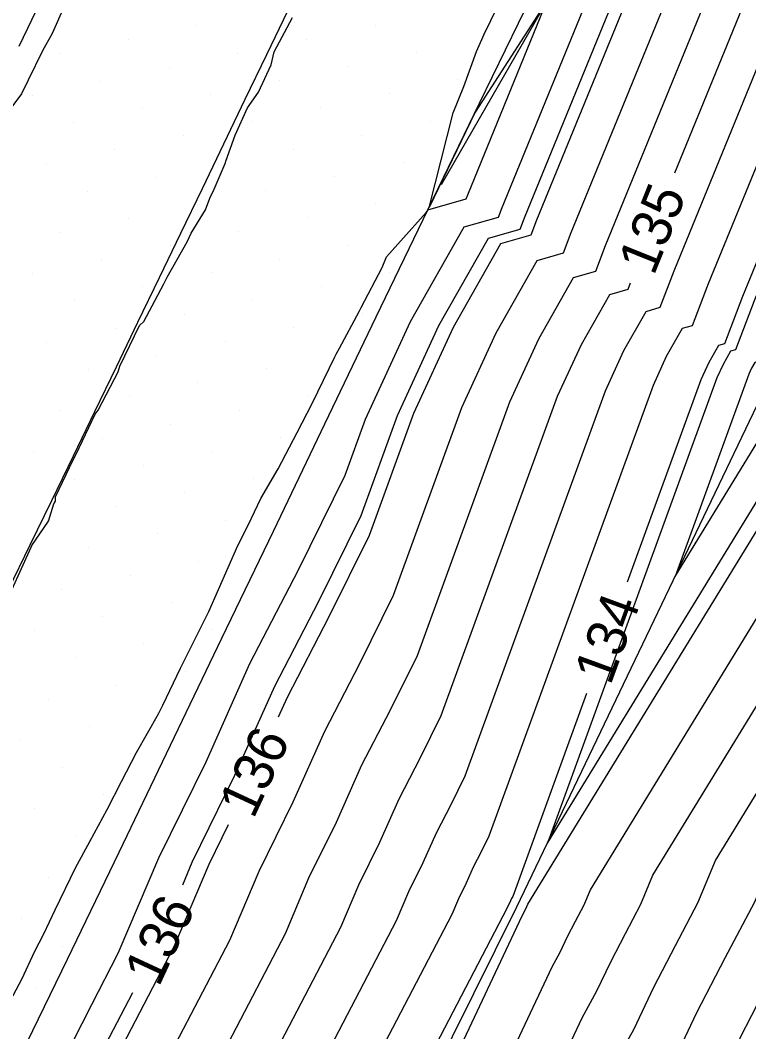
# Model space of a CAD drawing. Extents: x 2354170 to 2357230, y 866100 to 868290.
# Drawn here: x 2355241.8 to 2355278.6, y 866227 to 866278.1 of the extents above; entities that cross this region are included whole.
import ezdxf

# ---------------------------------------------------------------- set-up
doc = ezdxf.new("R2010")
doc.units = 0
for name, color, linetype in [('Default', 7, 'Continuous'), ('DTM Contours Major', 7, 'Continuous'), ('DTM Contours Major Text', 7, 'Continuous'), ('DTM Contours Minor', 7, 'Continuous'), ('DTM Contours Minor Text', 7, 'Continuous'), ('Exist DTM Breakline', 7, 'Continuous'), ('Exist DTM Scan Elevation Point', 7, 'Continuous'), ('Exist Roads EOP', 7, 'Continuous'), ('PH Exist DTM Breakline', 7, 'Continuous')]:
    doc.layers.add(name, color=color, linetype=linetype)

msp = doc.modelspace()

# ---------------------------------------------------------------- linework, layer by layer
at = {"layer": 'Default'}
for points in [[(2355317.189, 866360.801), (2355314.828, 866356.466), (2355312.404, 866351.964), (2355306.176, 866339.18), (2355300.829, 866329.165), (2355292.501, 866312.087), (2355288.744, 866303.483), (2355283.253, 866292.207), (2355282.594, 866289.072), (2355278.504, 866279.405), (2355274.815, 866270.385)], [(2355312.705, 866340.884), (2355312.471, 866340.403), (2355302.62, 866321.951), (2355298.281, 866313.055), (2355291.505, 866297.534), (2355288.645, 866291.66), (2355287.471, 866286.079), (2355280.19, 866268.873), (2355278.258, 866264.148), (2355277.348, 866261.759), (2355277.04, 866261.671), (2355276.558, 866260.821), (2355276.155, 866259.945), (2355272.434, 866249.729)], [(2355297.258, 866332.727), (2355286.72, 866311.12), (2355285.984, 866309.432), (2355277.862, 866292.755), (2355277.717, 866292.065), (2355276.817, 866289.938), (2355267.847, 866268.003), (2355267.559, 866267.247), (2355266.03, 866266.809), (2355263.633, 866262.589), (2355261.636, 866258.24), (2355259.392, 866252.08), (2355257.363, 866247.97), (2355255.249, 866243.896), (2355254.805, 866242.902)], [(2355240.662, 866218.818), (2355242.98, 866223.662), (2355245.376, 866228.393), (2355246.722, 866230.974), (2355248.773, 866235.801), (2355251.152, 866240.649), (2355253.369, 866245.609), (2355255.825, 866250.342), (2355258.182, 866255.118), (2355259.216, 866257.955), (2355261.479, 866262.883), (2355264.195, 866267.666), (2355265.927, 866268.161), (2355266.111, 866268.646), (2355275.282, 866291.07)], [(2355284.22, 866288.074), (2355279.066, 866275.895), (2355274.788, 866265.433), (2355274.085, 866263.588), (2355273.37, 866263.384), (2355272.25, 866261.41), (2355271.316, 866259.377), (2355264.23, 866239.927), (2355263.516, 866238.479), (2355262.771, 866237.044), (2355262.099, 866235.541), (2355261.379, 866234.072), (2355260.757, 866232.609), (2355252.064, 866215.937), (2355251.288, 866214.404), (2355250.537, 866212.835), (2355249.757, 866211.28), (2355248.995, 866209.715), (2355248.236, 866208.148), (2355238.535, 866189.512)], [(2355285.846, 866287.077), (2355279.628, 866272.384), (2355276.523, 866264.791), (2355275.717, 866262.673), (2355275.205, 866262.527), (2355274.404, 866261.115), (2355273.736, 866259.661), (2355265.44, 866236.888), (2355265.054, 866236.106), (2355264.652, 866235.332), (2355264.289, 866234.52), (2355263.9, 866233.726), (2355263.564, 866232.936), (2355253.401, 866213.445), (2355252.949, 866212.553), (2355252.512, 866211.638), (2355252.057, 866210.733), (2355251.614, 866209.821), (2355251.171, 866208.908), (2355239.816, 866187.091)], [(2355277.379, 866286.427), (2355269.582, 866267.361), (2355269.19, 866266.332), (2355267.865, 866265.953), (2355265.787, 866262.294), (2355264.056, 866258.524), (2355260.601, 866249.041), (2355258.901, 866245.597), (2355257.13, 866242.183), (2355255.531, 866238.606), (2355253.815, 866235.109), (2355252.336, 866231.628), (2355248.051, 866223.411), (2355246.303, 866219.959), (2355244.612, 866216.425), (2355242.855, 866212.923), (2355241.14, 866209.396)], [(2355289.097, 866285.082), (2355280.753, 866265.362), (2355279.994, 866263.506), (2355278.98, 866260.844), (2355278.875, 866260.814), (2355278.712, 866260.526), (2355278.575, 866260.229), (2355274.852, 866250.007), (2355280.494, 866259.216), (2355280.64, 866259.508), (2355280.781, 866259.807), (2355280.915, 866260.108), (2355282.395, 866262.573), (2355282.587, 866262.939), (2355282.747, 866263.309), (2355293.262, 866281.299)], [(2355277.941, 866282.916), (2355271.317, 866266.718), (2355270.822, 866265.417), (2355269.7, 866265.096), (2355267.941, 866261.999), (2355266.476, 866258.808), (2355261.811, 866246.003), (2355260.439, 866243.224), (2355259.01, 866240.47), (2355257.72, 866237.584), (2355256.336, 866234.763), (2355255.143, 866231.955), (2355249.389, 866220.919), (2355247.965, 866218.107), (2355246.587, 866215.228), (2355245.155, 866212.376), (2355243.758, 866209.502), (2355242.364, 866206.628), (2355235.975, 866194.353)], [(2355246.203, 866182.435), (2355246.567, 866183.488), (2355257.091, 866205.836), (2355257.531, 866206.727), (2355257.972, 866207.624), (2355258.438, 866208.514), (2355258.847, 866209.429), (2355259.237, 866210.329), (2355268.635, 866230.294), (2355269.043, 866231.029), (2355269.418, 866231.816), (2355269.821, 866232.596), (2355270.242, 866233.392), (2355270.569, 866234.185), (2355283.137, 866254.697), (2355283.85, 866256.129), (2355284.545, 866257.593), (2355285.198, 866259.066), (2355286.344, 866260.975), (2355287.134, 866262.474), (2355287.788, 866263.987), (2355295.93, 866277.918), (2355297.289, 866281.095)], [(2355248.794, 866182.033), (2355249.379, 866183.724), (2355258.397, 866202.874), (2355259.153, 866204.405), (2355259.91, 866205.944), (2355260.709, 866207.471), (2355261.412, 866209.043), (2355262.082, 866210.587), (2355270.146, 866227.718), (2355270.9, 866229.079), (2355271.596, 866230.536), (2355272.342, 866231.98), (2355273.12, 866233.454), (2355273.727, 866234.922), (2355284.459, 866252.438), (2355285.456, 866254.439), (2355286.427, 866256.485), (2355287.34, 866258.545), (2355288.319, 866260.176), (2355289.407, 866262.242), (2355290.308, 866264.325), (2355297.265, 866276.227), (2355299.022, 866280.337)], [(2355240.978, 866228.021), (2355241.862, 866229.694), (2355242.492, 866231.047), (2355242.966, 866231.961), (2355243.537, 866233.177), (2355244.555, 866235.285), (2355245.281, 866236.627), (2355246.166, 866238.239), (2355246.889, 866239.654), (2355247.638, 866241.117), (2355248.749, 866243.075), (2355248.971, 866243.514), (2355249.866, 866245.382), (2355250.009, 866245.685), (2355250.988, 866247.637), (2355251.293, 866248.239), (2355252.756, 866251.575), (2355253.274, 866252.6), (2355253.921, 866253.945), (2355254.794, 866255.449), (2355255.75, 866257.285), (2355256.516, 866258.752), (2355257.658, 866261.095), (2355257.72, 866261.242), (2355257.895, 866261.534), (2355258.89, 866263.393), (2355258.99, 866263.597), (2355260.05, 866265.623), (2355260.272, 866266.159), (2355262.273, 866268.389), (2355262.324, 866268.46), (2355262.36, 866268.522), (2355264.295, 866269.076), (2355264.376, 866269.288), (2355268.392, 866279.109), (2355264.753, 866273.46), (2355262.417, 866268.652), (2355263.644, 866273.432), (2355264.18, 866274.758), (2355264.82, 866276.531), (2355265.081, 866277.14), (2355265.129, 866277.25), (2355265.2, 866277.395), (2355266.224, 866279.523)], [(2355253.978, 866181.229), (2355255.004, 866184.197), (2355261.01, 866196.951), (2355262.396, 866199.759), (2355263.785, 866202.584), (2355265.252, 866205.385), (2355266.542, 866208.27), (2355267.772, 866211.104), (2355273.168, 866222.567), (2355274.615, 866225.179), (2355275.951, 866227.975), (2355277.383, 866230.748), (2355278.877, 866233.577), (2355280.042, 866236.395), (2355287.102, 866247.919), (2355288.666, 866251.06), (2355290.19, 866254.271), (2355291.624, 866257.503), (2355292.269, 866258.579), (2355293.953, 866261.776), (2355295.349, 866265.003), (2355299.933, 866272.846), (2355302.488, 866278.82)], [(2355241.341, 866249.335), (2355242.317, 866251.494), (2355242.357, 866251.578), (2355243.192, 866252.795), (2355243.465, 866253.68), (2355243.544, 866253.814), (2355243.551, 866254.023), (2355244.448, 866255.896), (2355244.596, 866256.183), (2355245.557, 866258.213), (2355245.709, 866258.412), (2355246.717, 866260.344), (2355246.794, 866260.638), (2355247.785, 866262.681), (2355248.003, 866262.891), (2355249.005, 866264.761), (2355249.193, 866265.127), (2355250.2, 866266.91), (2355250.398, 866267.355), (2355251.119, 866268.534), (2355251.348, 866269.126), (2355251.567, 866269.577), (2355252.125, 866270.866), (2355252.136, 866270.896), (2355252.16, 866270.989), (2355252.625, 866272.308), (2355253.25, 866273.681), (2355253.797, 866274.473), (2355254.451, 866275.856), (2355254.598, 866276.505), (2355255.52, 866278.243)], [(2355256.57, 866180.827), (2355257.816, 866184.433), (2355262.317, 866193.989), (2355264.018, 866197.436), (2355265.723, 866200.904), (2355267.524, 866204.342), (2355269.107, 866207.884), (2355270.616, 866211.362), (2355274.678, 866219.991), (2355276.473, 866223.229), (2355278.129, 866226.695), (2355279.904, 866230.131), (2355281.755, 866233.638), (2355283.199, 866237.132), (2355288.424, 866245.66), (2355290.272, 866249.37), (2355292.072, 866253.164), (2355293.766, 866256.983), (2355294.244, 866257.78), (2355296.226, 866261.544), (2355297.869, 866265.342), (2355301.267, 866271.156), (2355304.221, 866278.062), (2355304.538, 866278.526)], [(2355243.424, 866182.533), (2355243.611, 866182.837), (2355243.754, 866183.252), (2355255.784, 866208.798), (2355255.909, 866209.05), (2355256.034, 866209.304), (2355256.166, 866209.556), (2355256.282, 866209.816), (2355256.393, 866210.071), (2355267.125, 866232.87), (2355267.185, 866232.979), (2355267.241, 866233.096), (2355267.301, 866233.212), (2355267.363, 866233.33), (2355267.412, 866233.448), (2355281.816, 866256.957), (2355282.245, 866257.819), (2355282.663, 866258.7), (2355283.057, 866259.587), (2355284.369, 866261.774), (2355284.861, 866262.707), (2355285.268, 866263.648), (2355288.913, 866269.884)], [(2355272.574, 866264.819), (2355272.453, 866264.503), (2355271.535, 866264.24), (2355270.095, 866261.705), (2355268.896, 866259.092), (2355263.021, 866242.965), (2355261.978, 866240.852), (2355260.891, 866238.757), (2355259.91, 866236.563), (2355258.857, 866234.418), (2355257.95, 866232.282), (2355250.726, 866218.428), (2355249.626, 866216.256), (2355248.562, 866214.032), (2355247.456, 866211.828), (2355246.377, 866209.609), (2355245.3, 866207.388), (2355237.255, 866191.932)], [(2355251.386, 866181.631), (2355252.191, 866183.96), (2355259.704, 866199.913), (2355260.774, 866202.082), (2355261.847, 866204.264), (2355262.981, 866206.428), (2355263.977, 866208.657), (2355264.927, 866210.845), (2355271.657, 866225.143), (2355272.758, 866227.129), (2355273.774, 866229.255), (2355274.863, 866231.364), (2355275.999, 866233.515), (2355276.884, 866235.659), (2355285.781, 866250.179), (2355287.061, 866252.749), (2355288.309, 866255.378), (2355289.482, 866258.024), (2355290.294, 866259.377), (2355291.68, 866262.009), (2355292.447, 866263.781)], [(2355270.38, 866244.092), (2355266.65, 866233.85), (2355266.592, 866233.734), (2355266.532, 866233.619), (2355266.478, 866233.498), (2355266.421, 866233.38), (2355266.371, 866233.262), (2355254.739, 866210.954), (2355254.611, 866210.701), (2355254.487, 866210.442), (2355254.358, 866210.185), (2355254.232, 866209.927), (2355254.107, 866209.668), (2355241.096, 866184.671), (2355240.896, 866184.258), (2355240.697, 866183.846), (2355240.552, 866183.537), (2355240.052, 866183.756), (2355239.506, 866184.008), (2355238.678, 866184.415), (2355237.601, 866184.948), (2355231.837, 866187.859)], [(2355252.278, 866237.461), (2355251.294, 866235.455), (2355249.529, 866231.301), (2355246.713, 866225.902), (2355244.642, 866221.81), (2355242.637, 866217.621), (2355240.554, 866213.471), (2355238.521, 866209.29), (2355236.493, 866205.108), (2355233.415, 866199.194), (2355231.374, 866194.972), (2355229.337, 866190.749), (2355229.303, 866190.676), (2355224.187, 866192.916), (2355218.604, 866195.493), (2355210.125, 866199.659), (2355199.106, 866205.115), (2355186.262, 866211.604)]]:
    msp.add_lwpolyline(points, dxfattribs=at)
at = {"layer": 'DTM Contours Major'}
for points in [[(2355317.189, 866360.801), (2355314.828, 866356.466), (2355312.404, 866351.964), (2355306.176, 866339.18), (2355300.829, 866329.165), (2355292.501, 866312.087), (2355288.744, 866303.483), (2355283.253, 866292.207), (2355282.594, 866289.072), (2355278.504, 866279.405), (2355274.815, 866270.385)], [(2355272.574, 866264.819), (2355272.453, 866264.503), (2355271.535, 866264.24), (2355270.095, 866261.705), (2355268.896, 866259.092), (2355263.021, 866242.965), (2355261.978, 866240.852), (2355260.891, 866238.757), (2355259.91, 866236.563), (2355258.857, 866234.418), (2355257.95, 866232.282), (2355250.726, 866218.428), (2355249.626, 866216.256), (2355248.562, 866214.032), (2355247.456, 866211.828), (2355246.377, 866209.609), (2355245.3, 866207.388), (2355237.255, 866191.932)], [(2355251.386, 866181.631), (2355252.191, 866183.96), (2355259.704, 866199.913), (2355260.774, 866202.082), (2355261.847, 866204.264), (2355262.981, 866206.428), (2355263.977, 866208.657), (2355264.927, 866210.845), (2355271.657, 866225.143), (2355272.758, 866227.129), (2355273.774, 866229.255), (2355274.863, 866231.364), (2355275.999, 866233.515), (2355276.884, 866235.659), (2355285.781, 866250.179), (2355287.061, 866252.749), (2355288.309, 866255.378), (2355289.482, 866258.024), (2355290.294, 866259.377), (2355291.68, 866262.009), (2355292.447, 866263.781)]]:
    msp.add_lwpolyline(points, dxfattribs=at)
at = {"layer": 'DTM Contours Minor'}
for points in [[(2355249.973, 866234.439), (2355250.454, 866235.57), (2355252.611, 866239.968), (2355254.622, 866244.467), (2355256.85, 866248.76), (2355258.989, 866253.092), (2355260.829, 866258.145), (2355262.915, 866262.687), (2355265.418, 866267.095), (2355267.015, 866267.552), (2355267.268, 866268.217), (2355276.63, 866291.108)], [(2355288.013, 866285.747), (2355280.378, 866267.702), (2355278.837, 866263.934), (2355277.892, 866261.454), (2355277.652, 866261.385), (2355277.276, 866260.722), (2355276.962, 866260.04), (2355268.398, 866236.529), (2355281.375, 866257.71), (2355281.71, 866258.382), (2355282.036, 866259.069), (2355282.343, 866259.761), (2355283.711, 866262.04), (2355284.103, 866262.784), (2355284.428, 866263.535), (2355294.152, 866280.172)], [(2355243.966, 866278.765), (2355243.377, 866277.436), (2355242.887, 866276.568), (2355242.17, 866275.078), (2355241.823, 866274.388), (2355240.862, 866273.069)], [(2355177.84, 866215.898), (2355196.968, 866206.236), (2355208.539, 866200.506), (2355217.443, 866196.131), (2355223.306, 866193.425), (2355228.678, 866191.072), (2355228.706, 866191.132), (2355230.845, 866195.567), (2355232.988, 866200), (2355235.514, 866204.854), (2355237.648, 866209.255), (2355239.787, 866213.653), (2355241.979, 866218.02), (2355244.088, 866222.427), (2355246.268, 866226.732), (2355247.45, 866229)]]:
    msp.add_lwpolyline(points, dxfattribs=at)
at = {"layer": 'Exist DTM Breakline'}
for points in [[(2355255.288, 866278.603), (2355254.203, 866276.351), (2355253.119, 866274.098), (2355252.034, 866271.846), (2355250.95, 866269.593), (2355249.866, 866267.341), (2355248.78, 866265.088), (2355247.695, 866262.837), (2355246.609, 866260.585), (2355245.523, 866258.333), (2355244.434, 866256.083), (2355243.344, 866253.833), (2355242.254, 866251.583), (2355241.164, 866249.333)], [(2355241.711, 866276.789), (2355242.792, 866279.043)]]:
    msp.add_lwpolyline(points, dxfattribs=at)
at = {"layer": 'Exist DTM Scan Elevation Point'}
for p, q in [((2355250.682, 866277.816), (2355250.682, 866277.816)), ((2355259.696, 866277.848), (2355259.696, 866277.848)), ((2355247.217, 866277.11), (2355247.217, 866277.11)), ((2355256.231, 866277.142), (2355256.231, 866277.142)), ((2355265.245, 866277.174), (2355265.245, 866277.174)), ((2355243.753, 866276.405), (2355243.753, 866276.405)), ((2355252.767, 866276.436), (2355252.767, 866276.436)), ((2355261.781, 866276.468), (2355261.781, 866276.468)), ((2355249.302, 866275.731), (2355249.302, 866275.731)), ((2355258.316, 866275.763), (2355258.316, 866275.763)), ((2355245.838, 866275.025), (2355245.838, 866275.025)), ((2355254.852, 866275.057), (2355254.852, 866275.057)), ((2355263.866, 866275.089), (2355263.866, 866275.089)), ((2355242.374, 866274.32), (2355242.374, 866274.32)), ((2355251.387, 866274.351), (2355251.387, 866274.351)), ((2355260.401, 866274.383), (2355260.401, 866274.383)), ((2355247.923, 866273.646), (2355247.923, 866273.646)), ((2355256.937, 866273.678), (2355256.937, 866273.678)), ((2355253.472, 866272.972), (2355253.472, 866272.972)), ((2355262.486, 866273.004), (2355262.486, 866273.004)), ((2355244.459, 866272.94), (2355244.459, 866272.94)), ((2355250.008, 866272.267), (2355250.008, 866272.267)), ((2355259.022, 866272.298), (2355259.022, 866272.298)), ((2355246.544, 866271.561), (2355246.544, 866271.561)), ((2355255.557, 866271.593), (2355255.557, 866271.593)), ((2355261.107, 866270.919), (2355261.107, 866270.919)), ((2355243.079, 866270.855), (2355243.079, 866270.855)), ((2355252.093, 866270.887), (2355252.093, 866270.887)), ((2355248.629, 866270.182), (2355248.629, 866270.182)), ((2355257.642, 866270.213), (2355257.642, 866270.213)), ((2355245.164, 866269.476), (2355245.164, 866269.476)), ((2355254.178, 866269.508), (2355254.178, 866269.508)), ((2355250.714, 866268.802), (2355250.714, 866268.802)), ((2355259.727, 866268.834), (2355259.727, 866268.834)), ((2355247.249, 866268.097), (2355247.249, 866268.097)), ((2355256.263, 866268.128), (2355256.263, 866268.128)), ((2355243.785, 866267.391), (2355243.785, 866267.391)), ((2355252.799, 866267.423), (2355252.799, 866267.423)), ((2355249.334, 866266.717), (2355249.334, 866266.717)), ((2355258.348, 866266.749), (2355258.348, 866266.749)), ((2355245.87, 866266.012), (2355245.87, 866266.012)), ((2355254.884, 866266.043), (2355254.884, 866266.043)), ((2355242.405, 866265.306), (2355242.405, 866265.306)), ((2355251.419, 866265.338), (2355251.419, 866265.338)), ((2355260.433, 866265.369), (2355260.433, 866265.369)), ((2355247.955, 866264.632), (2355247.955, 866264.632)), ((2355256.969, 866264.664), (2355256.969, 866264.664)), ((2355244.49, 866263.927), (2355244.49, 866263.927)), ((2355253.504, 866263.958), (2355253.504, 866263.958)), ((2355250.04, 866263.253), (2355250.04, 866263.253)), ((2355259.054, 866263.284), (2355259.054, 866263.284)), ((2355246.575, 866262.547), (2355246.575, 866262.547)), ((2355255.589, 866262.579), (2355255.589, 866262.579)), ((2355243.111, 866261.842), (2355243.111, 866261.842)), ((2355252.125, 866261.873), (2355252.125, 866261.873)), ((2355257.674, 866261.199), (2355257.674, 866261.199)), ((2355248.66, 866261.168), (2355248.66, 866261.168)), ((2355245.196, 866260.462), (2355245.196, 866260.462)), ((2355254.21, 866260.494), (2355254.21, 866260.494)), ((2355250.745, 866259.788), (2355250.745, 866259.788)), ((2355247.281, 866259.083), (2355247.281, 866259.083)), ((2355256.295, 866259.114), (2355256.295, 866259.114)), ((2355243.816, 866258.377), (2355243.816, 866258.377)), ((2355252.83, 866258.409), (2355252.83, 866258.409)), ((2355249.366, 866257.703), (2355249.366, 866257.703)), ((2355245.901, 866256.998), (2355245.901, 866256.998)), ((2355254.915, 866257.029), (2355254.915, 866257.029)), ((2355242.437, 866256.292), (2355242.437, 866256.292)), ((2355251.451, 866256.324), (2355251.451, 866256.324)), ((2355247.986, 866255.618), (2355247.986, 866255.618)), ((2355244.522, 866254.913), (2355244.522, 866254.913)), ((2355253.536, 866254.944), (2355253.536, 866254.944)), ((2355250.071, 866254.239), (2355250.071, 866254.239)), ((2355246.607, 866253.533), (2355246.607, 866253.533)), ((2355243.143, 866252.828), (2355243.143, 866252.828)), ((2355252.156, 866252.859), (2355252.156, 866252.859)), ((2355248.692, 866252.154), (2355248.692, 866252.154)), ((2355245.228, 866251.448), (2355245.228, 866251.448)), ((2355250.777, 866250.774), (2355250.777, 866250.774)), ((2355247.313, 866250.069), (2355247.313, 866250.069)), ((2355243.848, 866249.363), (2355243.848, 866249.363)), ((2355249.397, 866248.689), (2355249.397, 866248.689)), ((2355245.933, 866247.984), (2355245.933, 866247.984)), ((2355242.469, 866247.278), (2355242.469, 866247.278)), ((2355251.482, 866247.31), (2355251.482, 866247.31)), ((2355248.018, 866246.604), (2355248.018, 866246.604)), ((2355244.554, 866245.899), (2355244.554, 866245.899)), ((2355250.103, 866245.225), (2355250.103, 866245.225)), ((2355246.639, 866244.519), (2355246.639, 866244.519)), ((2355243.174, 866243.814), (2355243.174, 866243.814)), ((2355248.724, 866243.14), (2355248.724, 866243.14)), ((2355245.259, 866242.434), (2355245.259, 866242.434)), ((2355241.795, 866241.729), (2355241.795, 866241.729)), ((2355247.344, 866241.055), (2355247.344, 866241.055)), ((2355243.88, 866240.35), (2355243.88, 866240.35)), ((2355245.965, 866238.97), (2355245.965, 866238.97)), ((2355242.5, 866238.265), (2355242.5, 866238.265)), ((2355244.585, 866236.885), (2355244.585, 866236.885)), ((2355243.206, 866234.8), (2355243.206, 866234.8)), ((2355241.826, 866232.715), (2355241.826, 866232.715)), ((2355243.911, 866231.336), (2355243.911, 866231.336)), ((2355242.532, 866229.251), (2355242.532, 866229.251))]:
    msp.add_line(p, q, dxfattribs=at)
at = {"layer": 'Exist Roads EOP'}
msp.add_lwpolyline([(2355225.817, 866192.888), (2355228.423, 866198.292), (2355231.034, 866203.694), (2355233.652, 866209.093), (2355236.276, 866214.489), (2355238.904, 866219.883), (2355241.53, 866225.278), (2355244.151, 866230.675), (2355246.762, 866236.077), (2355249.363, 866241.484), (2355251.959, 866246.893), (2355254.553, 866252.303), (2355257.149, 866257.713), (2355259.749, 866263.12), (2355262.355, 866268.524), (2355264.972, 866273.924), (2355267.599, 866279.318)], dxfattribs=at)
at = {"layer": 'PH Exist DTM Breakline'}
for points in [[(2355462.264, 866681.282), (2355449.29, 866652.845), (2355431.772, 866616.884), (2355416.85, 866585.734), (2355398.908, 866547.275), (2355381.513, 866510.255), (2355362.049, 866469.228), (2355342.769, 866429.753), (2355321.636, 866386.842), (2355298.704, 866337.728), (2355276.341, 866292.909), (2355263.024, 866269.789)], [(2355241.77, 866182.764), (2355241.927, 866183.098), (2355266.861, 866233.32), (2355281.117, 866263.09)]]:
    msp.add_lwpolyline(points, dxfattribs=at)

# ---------------------------------------------------------------- texts
at = {"layer": 'Default'}
for s, rotation, p in [('135', 68.0693, (2355273.769, 866265.153)), ('134', 69.9842, (2355271.579, 866244.46)), ('136', 65.0921, (2355253.542, 866237.707))]:
    msp.add_text(s, height=2, rotation=rotation, dxfattribs=at).set_placement(p)
at = {"layer": 'DTM Contours Major Text'}
msp.add_text('135', height=2, rotation=68.0693, dxfattribs=at).set_placement((2355273.769, 866265.153))
at = {"layer": 'DTM Contours Minor Text'}
msp.add_text('136', height=2, rotation=65.1135, dxfattribs=at).set_placement((2355248.762, 866229.221))

doc.saveas('drawing.dxf')
